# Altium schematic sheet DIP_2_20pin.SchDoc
size 381 x 241 mm
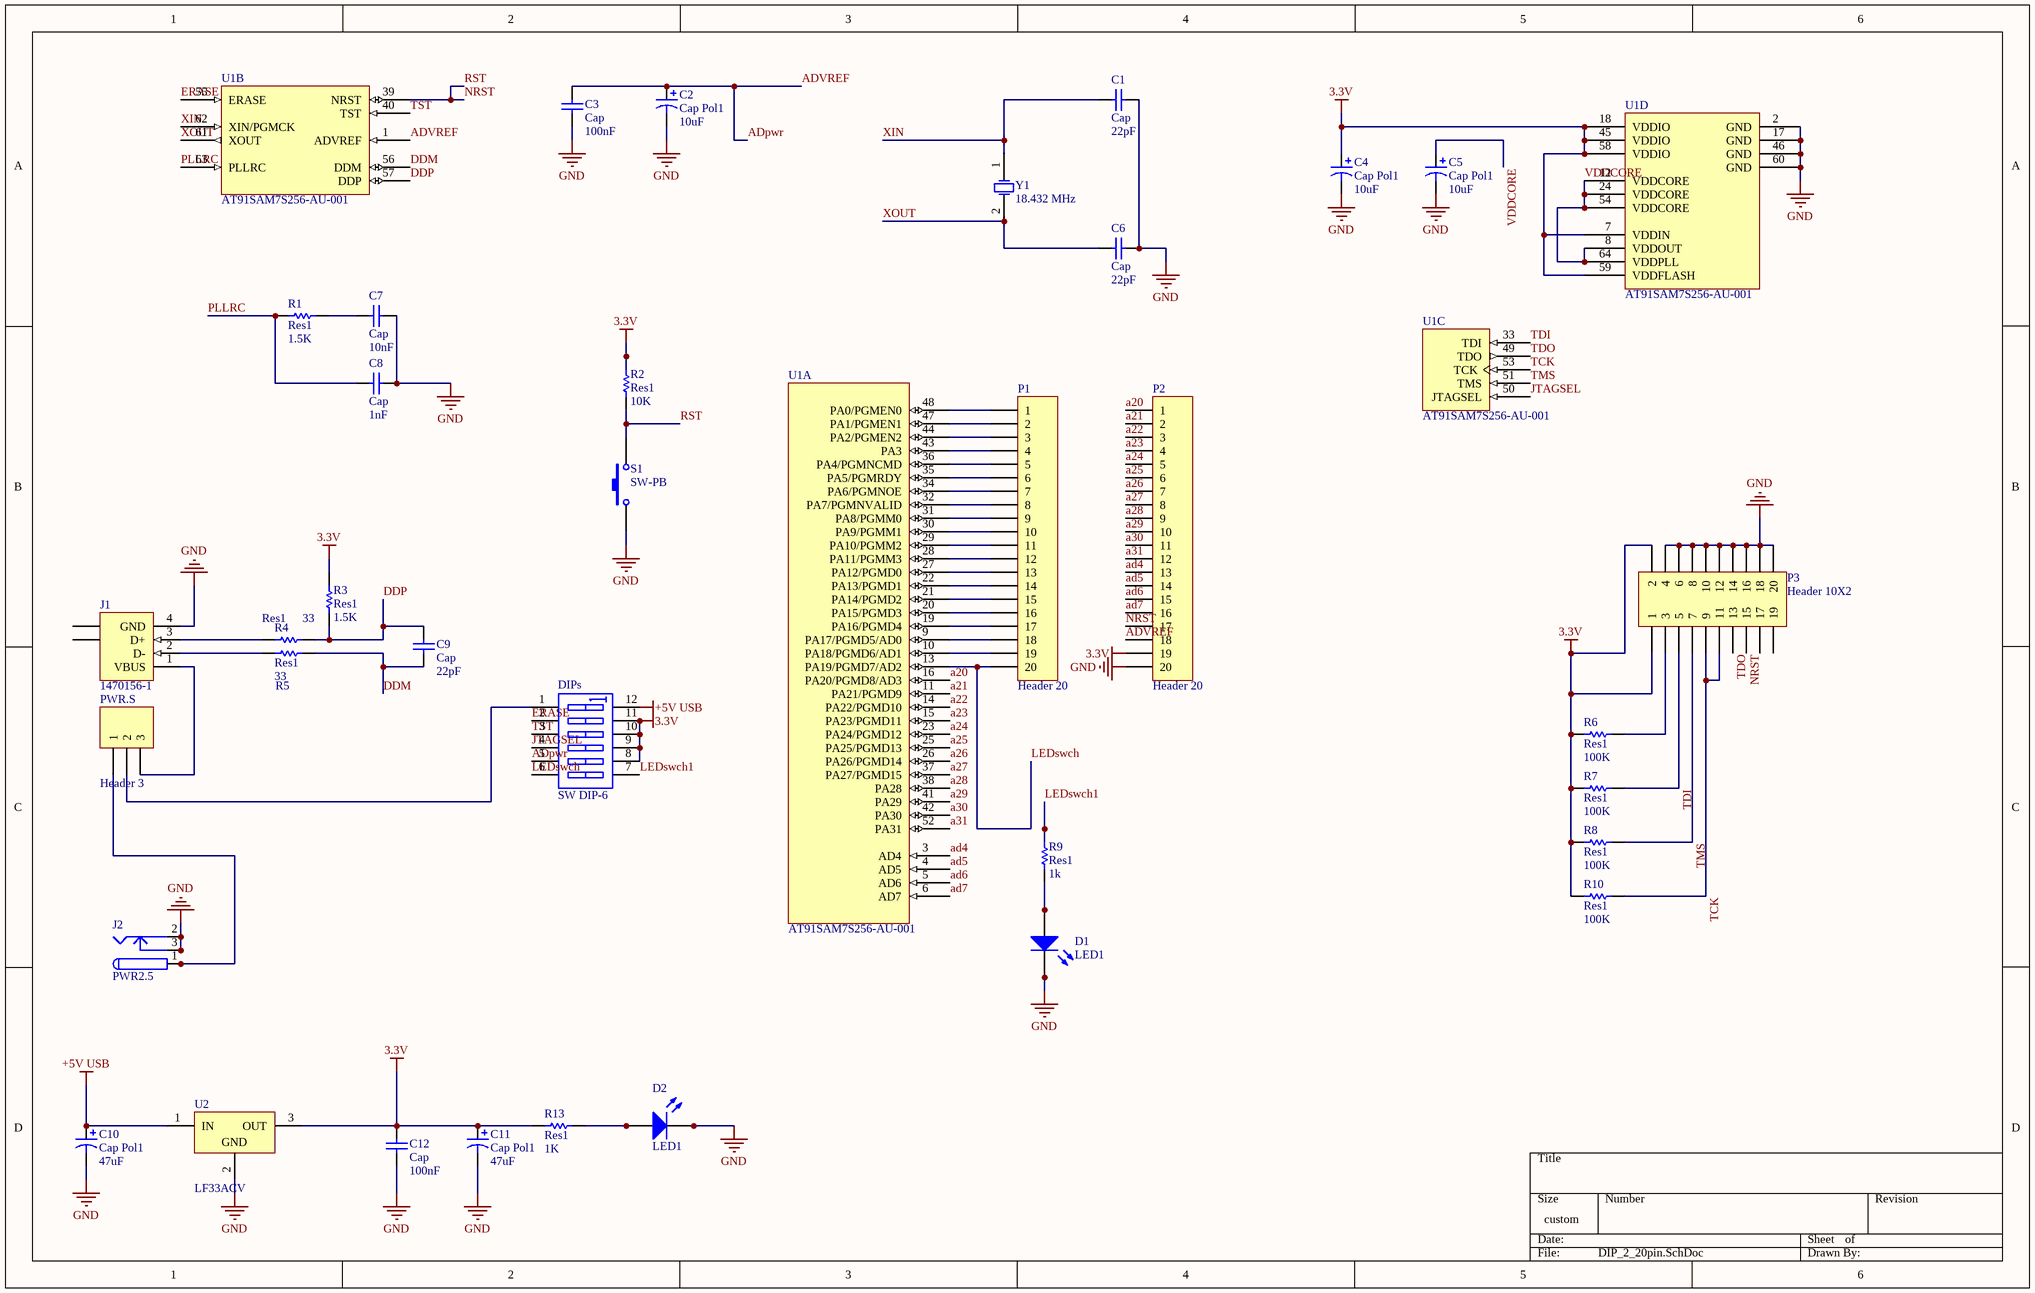
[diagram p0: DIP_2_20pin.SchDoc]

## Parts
C1  Cap  value 22pF  [VP32-3.2]
C2  Cap Pol1  value 10uF  [B]
C3  Cap  value 100nF  [VP32-3.2]
C4  Cap Pol1  value 10uF  [B]
C5  Cap Pol1  value 10uF  [B]
C6  Cap  value 22pF  [VP32-3.2]
C7  Cap  value 10nF  [VP32-3.2]
C8  Cap  value 1nF  [VP32-3.2]
C9  Cap  value 22pF  [VP32-3.2]
C10  Cap Pol1  value 47uF  [B]
C11  Cap Pol1  value 47uF  [B]
C12  Cap  value 100nF  [VP32-3.2]
D1  LED1  [LED-1]
D2  LED1  [LED-1]
DIPs  SW DIP-6  [DIP-12/SW]
J1  1470156-1  [1470156]
J2  PWR2.5  [KLD-0202]
P1  Header 20  [HDR1X20]
P2  Header 20  [HDR1X20]
P3  Header 10X2  [HDR2X10]
PWR.S  Header 3  [HDR1X3]
R1  Res1  value 1.5K  [AXIAL-0.3]
R2  Res1  value 10K  [AXIAL-0.3]
R3  Res1  value 1.5K  [AXIAL-0.3]
R4  Res1  value 33  [AXIAL-0.3]
R5  Res1  value 33  [AXIAL-0.3]
R6  Res1  value 100K  [AXIAL-0.3]
R7  Res1  value 100K  [AXIAL-0.3]
R8  Res1  value 100K  [AXIAL-0.3]
R9  Res1  value 1k  [AXIAL-0.3]
R10  Res1  value 100K  [AXIAL-0.3]
R13  Res1  value 1K  [AXIAL-0.3]
S1  SW-PB  [SPST-2]
U1  AT91SAM7S256-AU-001  [LQFP64_L]  (parts A,B,C,D of 4)
U2  LF33ACV  [TO-220A]
Y1  18.432 MHz  [HC-49U]

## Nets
3.3V: C4.1 C11.1 C12.2 DIPs.8(B5) DIPs.9(B4) DIPs.10(B3) DIPs.11(B2) P2.19 P3.1 P3.2 R2.2 R3.1 R6.1 R7.1 R8.1 R10.1 R13.1 U1.7(VDDIN) U1.18(VDDIO) U1.45(VDDIO) U1.58(VDDIO) U1.59(VDDFLASH) U2.3(OUT)
+5V USB: C10.1 DIPs.12(B1) U2.1(IN)
GND: C1.2 C2.2 C3.1 C4.2 C5.2 C6.2 C7.2 C8.2 C10.2 C11.2 C12.1 D1.2(K) D2.2(K) J1.4(GND) J2.2 J2.2A J2.2B J2.3 J2.3A J2.3B P2.20 P3.4 P3.6 P3.8 P3.10 P3.12 P3.14 P3.16 P3.18 P3.20 S1.1 U1.2(GND) U1.17(GND) U1.46(GND) U1.60(GND) U2.2(GND)
a20: P2.1 U1.16(PA20/PGMD8/AD3)
a21: P2.2 U1.11(PA21/PGMD9)
a22: P2.3 U1.14(PA22/PGMD10)
a23: P2.4 U1.15(PA23/PGMD11)
a24: P2.5 U1.23(PA24/PGMD12)
a25: P2.6 U1.25(PA25/PGMD13)
a26: P2.7 U1.26(PA26/PGMD14)
a27: P2.8 U1.37(PA27/PGMD15)
a28: P2.9 U1.38(PA28)
a29: P2.10 U1.41(PA29)
a30: P2.11 U1.42(PA30)
a31: P2.12 U1.52(PA31)
ad4: P2.13 U1.3(AD4)
ad5: P2.14 U1.4(AD5)
ad6: P2.15 U1.5(AD6)
ad7: P2.16 U1.6(AD7)
ADpwr: C2.1 C3.2 DIPs.5(A5) P2.18 U1.1(ADVREF)  [also labelled ADVREF]
DDM: C9.1 R5.2 U1.56(DDM)
DDP: C9.2 R3.2 R4.2 U1.57(DDP)
ERASE: DIPs.2(A2) U1.55(ERASE)
JTAGSEL: DIPs.4(A4) U1.50(JTAGSEL)
LEDswch: DIPs.6(A6) P1.20 U1.13(PA19/PGMD7/AD2)
LEDswch1: DIPs.7(B6) R9.2
NRST: P2.17 P3.15 R2.1 S1.2 U1.39(NRST)  [also labelled RST]
PLLRC: C8.1 R1.1 U1.63(PLLRC)
TCK: P3.9 P3.11 R10.2 U1.53(TCK)
TDI: P3.5 R7.2 U1.33(TDI)
TDO: P3.13 U1.49(TDO)
TMS: P3.7 R8.2 U1.51(TMS)
TST: DIPs.3(A3) U1.40(TST)
VDDCORE: C5.1 U1.8(VDDOUT) U1.12(VDDCORE) U1.24(VDDCORE) U1.54(VDDCORE) U1.64(VDDPLL)
XIN: C1.1 U1.62(XIN/PGMCK) Y1.1(OSC1)
XOUT: C6.1 U1.61(XOUT) Y1.2(OSC2)
NetC7_1: C7.1 R1.2
NetD1_1: D1.1(A) R9.1
NetD2_1: D2.1(A) R13.2
NetDIPs_1: DIPs.1(A1) PWR.S.2
NetJ1_1: J1.1(VBUS) PWR.S.3
NetJ1_2: J1.2(D-) R5.1
NetJ1_3: J1.3(D+) R4.1
NetJ2_1: J2.1 J2.1A J2.1B PWR.S.1
NetP1_1: P1.1 U1.48(PA0/PGMEN0)
NetP1_2: P1.2 U1.47(PA1/PGMEN1)
NetP1_3: P1.3 U1.44(PA2/PGMEN2)
NetP1_4: P1.4 U1.43(PA3)
NetP1_5: P1.5 U1.36(PA4/PGMNCMD)
NetP1_6: P1.6 U1.35(PA5/PGMRDY)
NetP1_7: P1.7 U1.34(PA6/PGMNOE)
NetP1_8: P1.8 U1.32(PA7/PGMNVALID)
NetP1_9: P1.9 U1.31(PA8/PGMM0)
NetP1_10: P1.10 U1.30(PA9/PGMM1)
NetP1_11: P1.11 U1.29(PA10/PGMM2)
NetP1_12: P1.12 U1.28(PA11/PGMM3)
NetP1_13: P1.13 U1.27(PA12/PGMD0)
NetP1_14: P1.14 U1.22(PA13/PGMD1)
NetP1_15: P1.15 U1.21(PA14/PGMD2)
NetP1_16: P1.16 U1.20(PA15/PGMD3)
NetP1_17: P1.17 U1.19(PA16/PGMD4)
NetP1_18: P1.18 U1.9(PA17/PGMD5/AD0)
NetP1_19: P1.19 U1.10(PA18/PGMD6/AD1)
NetP3_3: P3.3 R6.2

Not connected (* = marked no-connect by the designer): J1 5(SHLD) 6(SHLD); P3 17 19

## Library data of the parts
C1 C3 C6-C9 C12 = Cap: Capacitor
C2 C4 C5 C10 C11 = Cap Pol1: Polarized Capacitor (Radial)
D1 D2 = LED1: Typical RED GaAs LED
DIPs = SW DIP-6: DIP Switch, 6 Position, SPST
J1 = 1470156-1: USB 1.1, Right Angle, Thru-Hole, B Type, Receptacle, 4 Position, White; ContactMaterial: Phosphor Bronze; ContactPlating: Gold over Nickel; TerminationLength: 3.00mm [0.118in.]; PCB_Layout: Complies with manufacturer's recommendation.; DrillSize: Corresponds to nominal value.; PanelGround: Without
J2 = PWR2.5: Low Voltage Power Supply Connector
P1 P2 = Header 20: Header, 20-Pin
P3 = Header 10X2: Header, 10-Pin, Dual row
PWR.S = Header 3: Header, 3-Pin
R1-R10 R13 = Res1: Resistor
S1 = SW-PB: Switch
U1 = AT91SAM7S256-AU-001: Smart ARM Microcontroller, ARM7TDMI 32-Bit RISC CPU, 256KB Flash and 64KB SRAM, 64-Pin LQFP, Industrial, Pb-Free
U2 = LF33ACV: 500mA, Very Low Drop (0.45V) Voltage Regulator with Dump Protection (40V)
Y1 = ECS-10-13-1: Crystal Oscillator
